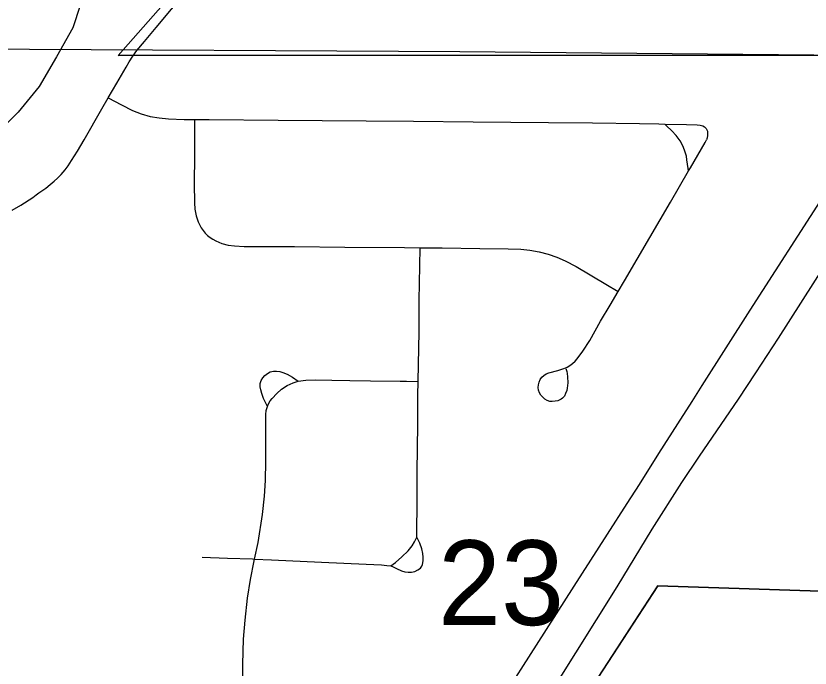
# Model space of a CAD drawing. Extents: x 0 to 34, y 0 to 22.
# Drawn here: x 7.0428 to 7.435, y 20.079 to 20.4014 of the extents above; entities that cross this region are included whole.
import ezdxf

# ---------------------------------------------------------------- set-up
doc = ezdxf.new("R2010")
doc.units = 0
for name, color, linetype in [('GM_X_City_Street', 7, 'Continuous'), ('GM_X_Corporation', 7, 'Continuous'), ('GM_X_Interstate_Route', 7, 'Continuous'), ('GM_X_Minor_River', 7, 'Continuous'), ('GM_X_Section_Text', 7, 'Continuous'), ('GM_X_Township_Road', 7, 'Continuous')]:
    doc.layers.add(name, color=color, linetype=linetype)

msp = doc.modelspace()

# ---------------------------------------------------------------- linework, layer by layer
at = {"layer": 'GM_X_City_Street'}
for points in [[(7.08832, 20.36089), (7.09496, 20.35743), (7.1004, 20.3546), (7.10467, 20.35298), (7.10905, 20.35175), (7.11354, 20.35095), (7.11811, 20.35051), (7.12581, 20.35021), (7.13095, 20.35021), (7.1382, 20.35021), (7.17236, 20.34987), (7.19408, 20.34963), (7.21579, 20.34947), (7.23907, 20.34942), (7.26855, 20.34909), (7.3058, 20.34876), (7.32751, 20.3485), (7.3508, 20.34824), (7.36033, 20.34801), (7.36329, 20.34794), (7.37399, 20.34769), (7.37931, 20.34757), (7.3807, 20.34745), (7.38136, 20.3473), (7.38198, 20.34707), (7.38295, 20.3465), (7.38376, 20.34567), (7.38405, 20.34504), (7.38428, 20.3444), (7.38443, 20.34307), (7.38441, 20.34229), (7.38418, 20.34113), (7.38383, 20.3401)], [(7.13095, 20.35021), (7.13095, 20.34161), (7.13094, 20.33233), (7.13076, 20.31836), (7.1309, 20.309), (7.13115, 20.3058), (7.1318, 20.30264), (7.13286, 20.2996), (7.13429, 20.2967), (7.13518, 20.29532), (7.13623, 20.29403), (7.13742, 20.29287), (7.13871, 20.29187), (7.14007, 20.29097), (7.14149, 20.29018), (7.14449, 20.28895), (7.14762, 20.28814), (7.15078, 20.2877), (7.1555, 20.28747), (7.18037, 20.28748), (7.2052, 20.28704), (7.23471, 20.28687), (7.24237, 20.28683), (7.25334, 20.28678), (7.27198, 20.28641), (7.28594, 20.28629), (7.29208, 20.28609), (7.29665, 20.28563), (7.30115, 20.2848), (7.30558, 20.28363), (7.30992, 20.2822), (7.3141, 20.28037), (7.31954, 20.27752), (7.33421, 20.26874), (7.34025, 20.26512)], [(7.37503, 20.32481), (7.37485, 20.326), (7.37421, 20.33029), (7.3739, 20.33206), (7.37356, 20.33347), (7.37305, 20.33504), (7.3722, 20.33713), (7.37085, 20.33962), (7.36887, 20.34235), (7.36673, 20.34466), (7.36418, 20.34709), (7.36329, 20.34794)], [(7.31438, 20.22708), (7.3148, 20.2256), (7.31499, 20.22459), (7.3152, 20.22302), (7.31529, 20.2201), (7.31507, 20.21742), (7.3148, 20.21624), (7.31425, 20.21467), (7.31365, 20.2135), (7.31279, 20.2125), (7.31202, 20.21195), (7.31134, 20.21156), (7.31048, 20.21119), (7.30912, 20.21088), (7.30771, 20.21077), (7.30644, 20.21083), (7.30521, 20.21122), (7.30403, 20.21195), (7.30297, 20.21286), (7.30206, 20.21395), (7.30134, 20.21513), (7.30088, 20.21639), (7.30069, 20.21769), (7.30081, 20.21904), (7.30119, 20.2204), (7.30177, 20.22167), (7.30254, 20.2228), (7.30349, 20.22371), (7.30463, 20.22444), (7.30597, 20.22497), (7.3104, 20.22613), (7.31347, 20.2271), (7.31496, 20.2278), (7.31637, 20.22862), (7.3177, 20.2296), (7.31892, 20.2307), (7.32001, 20.2319), (7.32282, 20.23573), (7.32619, 20.241), (7.33153, 20.25048), (7.33625, 20.25846), (7.34025, 20.26512), (7.34343, 20.27042), (7.35584, 20.29189), (7.36601, 20.30928), (7.37503, 20.32481), (7.37592, 20.32634), (7.3832, 20.33887), (7.38383, 20.3401)], [(7.24264, 20.12848), (7.24318, 20.12932), (7.24364, 20.13022), (7.24383, 20.13103), (7.24398, 20.13219), (7.24395, 20.13381), (7.2438, 20.13562), (7.24329, 20.13797), (7.24226, 20.14075), (7.24164, 20.14212), (7.24078, 20.14366), (7.24093, 20.16293), (7.24103, 20.17609), (7.24121, 20.19946), (7.24131, 20.21393), (7.24146, 20.22074), (7.24182, 20.23728), (7.24187, 20.24509), (7.24198, 20.26067), (7.24224, 20.2778), (7.24237, 20.28683)], [(7.16698, 20.20835), (7.16511, 20.21226), (7.16422, 20.2147), (7.16369, 20.21652), (7.1634, 20.21807), (7.16346, 20.21965), (7.1639, 20.22117), (7.16469, 20.22253), (7.16575, 20.22371), (7.167, 20.2247), (7.16841, 20.2254), (7.16994, 20.22576), (7.17151, 20.2258), (7.17309, 20.22555), (7.1746, 20.22509), (7.17682, 20.22429), (7.17942, 20.22289), (7.18224, 20.22091)], [(7.15479, 20.06464), (7.15481, 20.0809), (7.15524, 20.09338), (7.15594, 20.1027), (7.15714, 20.11357), (7.15856, 20.12283), (7.16046, 20.13199), (7.16065, 20.13289), (7.16234, 20.1411), (7.16452, 20.15486), (7.16559, 20.16406), (7.16605, 20.17177), (7.16614, 20.18106), (7.16623, 20.19816), (7.16627, 20.20436), (7.16643, 20.20633), (7.16698, 20.20835), (7.16756, 20.20962), (7.16841, 20.21104), (7.16938, 20.21235), (7.17158, 20.21471), (7.174, 20.21682), (7.17669, 20.21862), (7.17963, 20.22), (7.18224, 20.22091), (7.18593, 20.2214), (7.19068, 20.22153), (7.19884, 20.22138), (7.20772, 20.22122), (7.21792, 20.22103), (7.23255, 20.22076), (7.23562, 20.22076), (7.24146, 20.22074)], [(7.22801, 20.1295), (7.23025, 20.13122), (7.23345, 20.13396), (7.23659, 20.13705), (7.2385, 20.13949), (7.23967, 20.14135), (7.24078, 20.14366)], [(7.13481, 20.13391), (7.14724, 20.13337), (7.15966, 20.13294), (7.16065, 20.13289), (7.16897, 20.13253), (7.19376, 20.13138), (7.2158, 20.13037), (7.22326, 20.13002), (7.226, 20.12978), (7.22801, 20.1295), (7.22913, 20.12903), (7.2308, 20.12824), (7.2332, 20.1271), (7.23484, 20.12661), (7.23645, 20.12637), (7.23812, 20.12641), (7.23972, 20.12679), (7.24131, 20.12751), (7.24264, 20.12848)]]:
    msp.add_lwpolyline(points, dxfattribs=at)
at = {"layer": 'GM_X_Corporation'}
for points in [[(7.0256, 19.8962), (7.07686, 19.89321), (7.11748, 19.88961), (7.11771, 19.89655), (7.13339, 19.8964), (7.13363, 19.9083), (7.15403, 19.90741), (7.15583, 19.90986), (7.15588, 19.89217), (7.21817, 19.89124), (7.22492, 19.90724), (7.27421, 19.98794), (7.35988, 20.11968), (7.54027, 20.11381), (7.54207, 20.38207), (7.09324, 20.38188), (7.12286, 20.41555)], [(7.12286, 20.41555), (7.09324, 20.38188), (7.54207, 20.38207), (7.54027, 20.11381), (7.35988, 20.11968), (7.29067, 20.01348), (7.27421, 19.98794), (7.22492, 19.90724), (7.21786, 19.8905), (7.36596, 19.88863), (7.36601, 19.88935), (7.36669, 19.88935), (7.36724, 19.89727), (7.39308, 19.88877), (8.01747, 19.88254)]]:
    msp.add_lwpolyline(points, dxfattribs=at)
msp.add_lwpolyline([(7.26206, 20.38382), (7.54168, 20.38124), (7.54127, 19.86087), (7.01866, 19.89693), (7.01906, 20.14488), (7.01904, 20.38509)], close=True, dxfattribs=at)
at = {"layer": 'GM_X_Interstate_Route'}
for points in [[(7.33967, 20.11913), (7.35696, 20.14763), (7.37173, 20.17071), (7.38034, 20.18369), (7.39964, 20.21195), (7.40824, 20.22488), (7.41935, 20.24211), (7.45483, 20.29769), (7.45603, 20.29955), (7.4589, 20.30396), (7.46709, 20.31645), (7.47652, 20.33109), (7.49356, 20.35782), (7.50805, 20.38026)], [(7.27805, 20.05604), (7.29614, 20.08433), (7.31846, 20.11945), (7.33492, 20.14519), (7.3446, 20.16042), (7.35069, 20.16983), (7.36036, 20.18507), (7.36968, 20.19974), (7.37672, 20.21081), (7.38166, 20.21872), (7.40546, 20.25594), (7.44145, 20.31199)], [(7.0969, 19.74629), (7.11455, 19.76875), (7.12533, 19.78391), (7.13408, 19.79673), (7.14857, 19.81842), (7.1631, 19.84084), (7.17018, 19.85181), (7.18303, 19.87164), (7.19352, 19.88801), (7.21355, 19.91928), (7.25168, 19.97901), (7.27932, 20.02257), (7.33967, 20.11913)]]:
    msp.add_lwpolyline(points, dxfattribs=at)
at = {"layer": 'GM_X_Minor_River'}
msp.add_lwpolyline([(7.07445, 20.40648), (7.07091, 20.39552), (7.06279, 20.3812), (7.05428, 20.36651), (7.04391, 20.35374), (7.03435, 20.34437)], dxfattribs=at)
at = {"layer": 'GM_X_Township_Road'}
for points in [[(7.10045, 20.38155), (7.10257, 20.38431), (7.10623, 20.38874), (7.11207, 20.39567), (7.12723, 20.41389), (7.13712, 20.42508)], [(7.08832, 20.36089), (7.09263, 20.36823), (7.09724, 20.37612), (7.09868, 20.37873), (7.10045, 20.38155)], [(7.04091, 20.30534), (7.04525, 20.30792), (7.05105, 20.3117), (7.05284, 20.31289), (7.05408, 20.31386), (7.05752, 20.31631), (7.05977, 20.31806), (7.06162, 20.31971), (7.06337, 20.32118), (7.06512, 20.32294), (7.06707, 20.32528), (7.06853, 20.32723), (7.07029, 20.32986), (7.07311, 20.33454), (7.07642, 20.3401), (7.08513, 20.35545), (7.08832, 20.36089)]]:
    msp.add_lwpolyline(points, dxfattribs=at)

# ---------------------------------------------------------------- texts
at = {"layer": 'GM_X_Section_Text'}
msp.add_text('23', height=0.041856, rotation=0, dxfattribs=at).set_placement((7.25124, 20.10029))

doc.saveas('drawing.dxf')
